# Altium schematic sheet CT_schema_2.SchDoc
size 240 x 321 mm
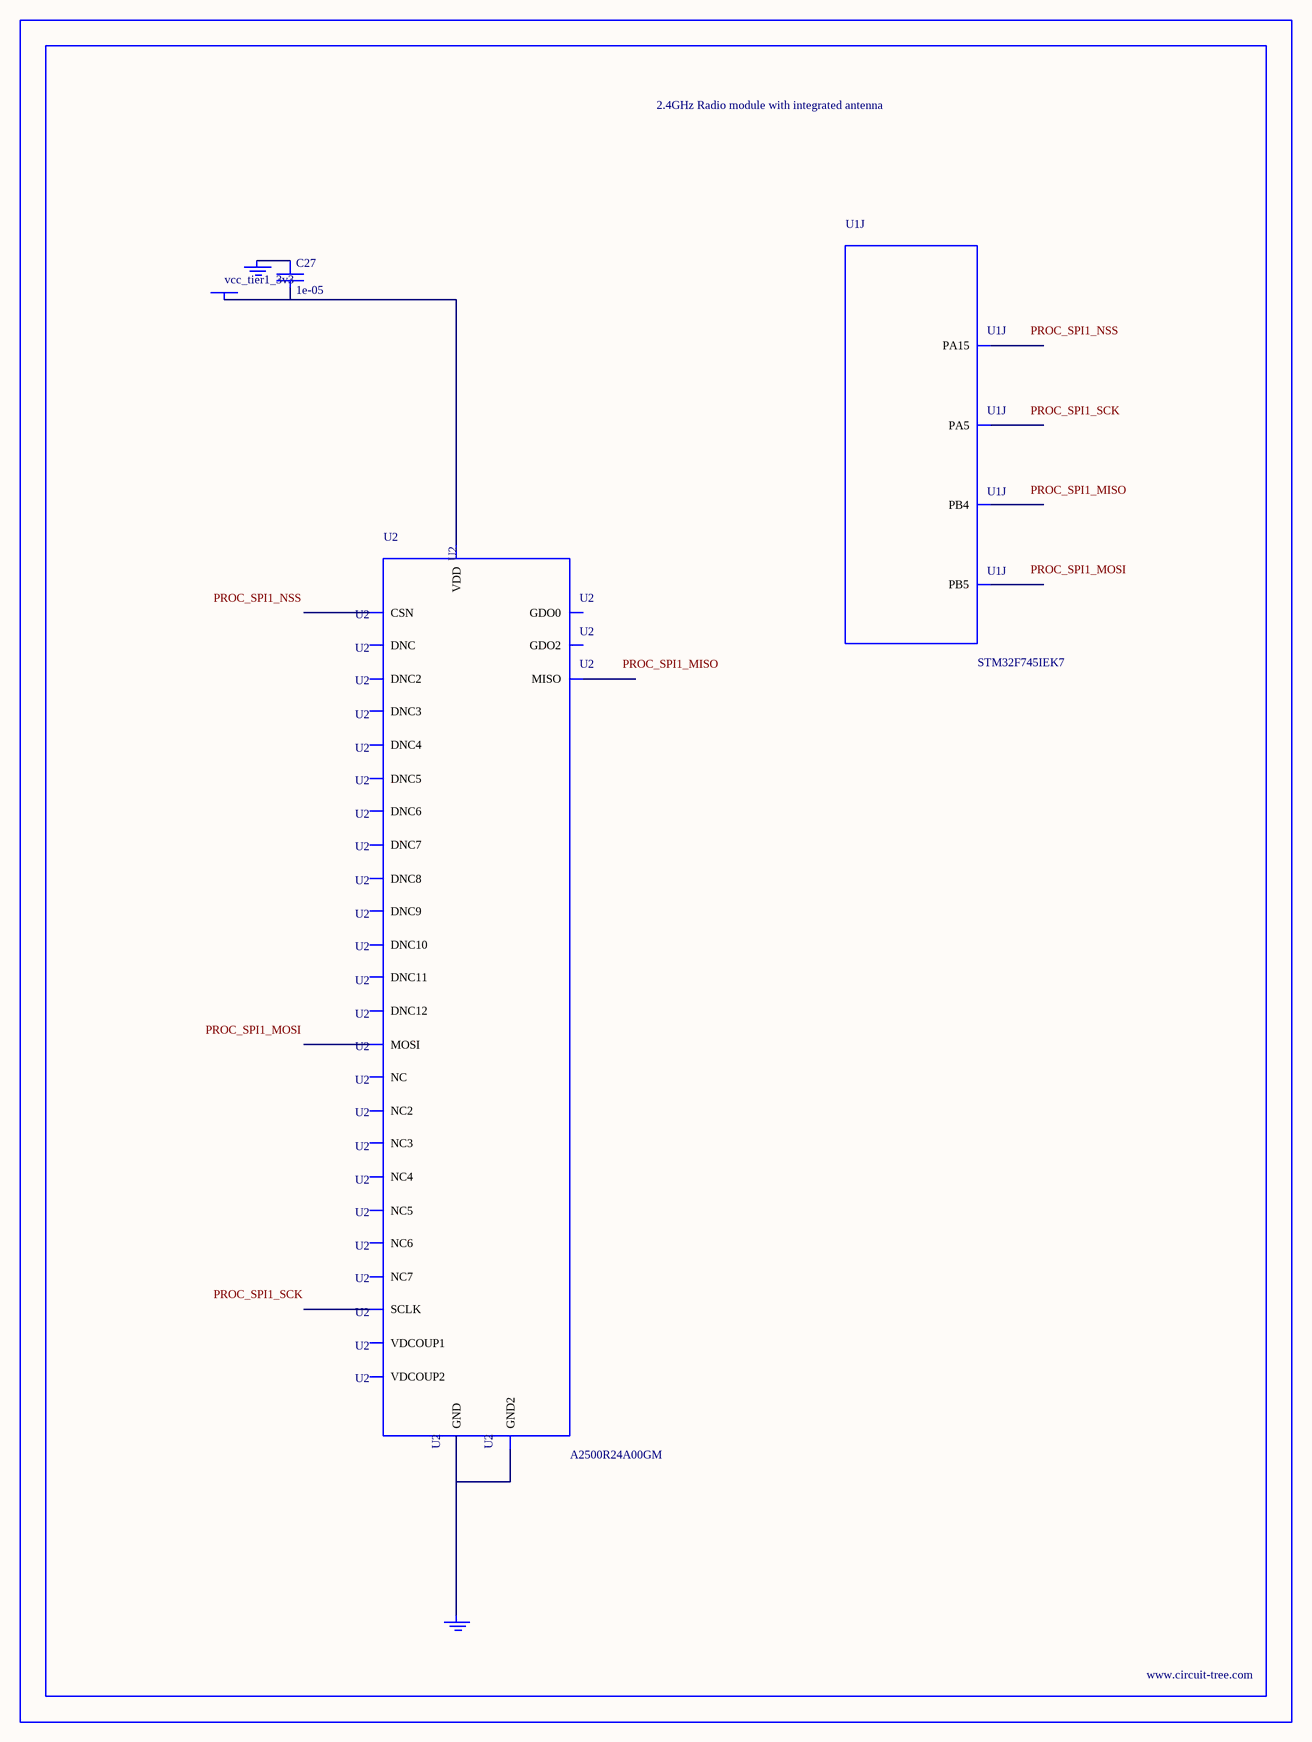
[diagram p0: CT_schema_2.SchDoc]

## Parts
BORDER1  (no value)
C27  1e-05  [C0805]
GND_INSTANCE_1_0  (no value)
GND_INSTANCE_1_1  (no value)
POWER_INSTANCE_1_0  vcc_tier1_3v3
U1  STM32F745IEK7  [UFBGA176_25]  (part J of 14)
U2  A2500R24A00GM  [A2500R24A00GM]

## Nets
NetC27_1: C27.1 GND_INSTANCE_1_0.0(GND)
NetC27_2: C27.2 POWER_INSTANCE_1_0.0(PWR) U2.18(VDD)
NetGND_INSTANCE_1_1_0: GND_INSTANCE_1_1.0(GND) U2.8(GND) U2.17(GND2)

Not connected (* = marked no-connect by the designer): U1 A6(PB5) A9(PB4) A13(PA15) P4(PA5); U2 1(DNC) 2(DNC2) 3(DNC3) 4(NC) 5(NC2) 6(NC3) 7(VDCOUP1) 9(SCLK) 10(MISO) 11(MOSI) 12(CSN) 13(GDO0) 14(GDO2) 15(VDCOUP2) 16(NC4) 19(NC5) 20(NC6) 21(NC7) 22(DNC4) 23(DNC5) 24(DNC6) 25(DNC7) 26(DNC8) 27(DNC9) 28(DNC10) 29(DNC11) 30(DNC12)

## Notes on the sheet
- Labels drawn without touching a wire or pin: PROC_SPI1_MISO, PROC_SPI1_MOSI, PROC_SPI1_NSS, PROC_SPI1_SCK

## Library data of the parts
BORDER1 = BORDER_PAGE1
C27 = C0805C106K8RACTU
GND_INSTANCE_1_0 GND_INSTANCE_1_1 = GND
POWER_INSTANCE_1_0 = PWR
